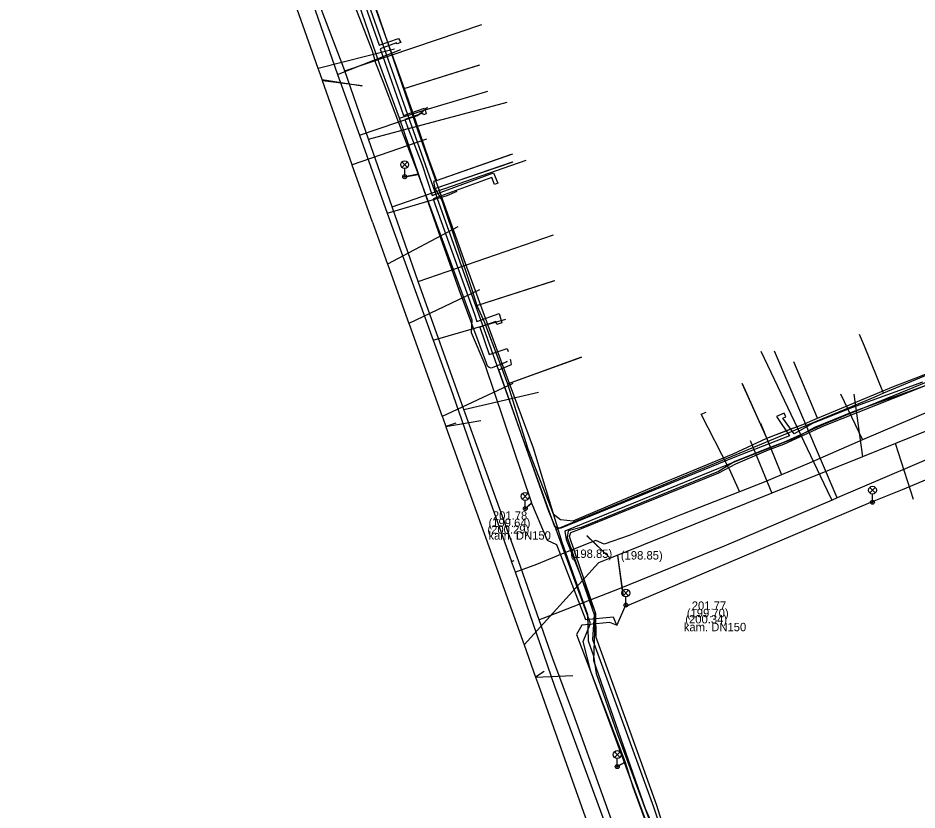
# Model space of a CAD drawing. Extents: x -596228 to -595156, y -1161235 to -1159373.
# Drawn here: x -596054.9 to -595969.3, y -1160804.7 to -1160729.3 of the extents above; entities that cross this region are included whole.
import ezdxf

# ---------------------------------------------------------------- set-up
doc = ezdxf.new("R2010")
doc.units = 0
for name, color, linetype in [('Vrstva 1', 7, 'Continuous'), ('Vrstva 12', 7, 'Continuous'), ('Vrstva 14', 7, 'Continuous'), ('Vrstva 19', 7, 'Continuous'), ('Vrstva 33', 7, 'Continuous'), ('Vrstva 42', 7, 'Continuous'), ('Vrstva 44', 7, 'Continuous'), ('Vrstva 55', 7, 'Continuous'), ('Vrstva 58', 7, 'Continuous'), ('Vrstva 9', 7, 'Continuous')]:
    doc.layers.add(name, color=color, linetype=linetype)

msp = doc.modelspace()

# ---------------------------------------------------------------- linework, layer by layer
at = {"layer": 'Vrstva 1'}
for p, q in [((-596025.96, -1160735.15), (-596022.13, -1160735.76)), ((-596022.13, -1160735.76), (-596025.918, -1160735.267)), ((-596014.19, -1160768.15), (-596010.85, -1160767.6)), ((-596013.241, -1160767.843), (-596014.193, -1160768.15)), ((-596000.757, -1160778.554), (-595998.525, -1160780.718)), ((-596000.75, -1160778.55), (-595998.541, -1160780.7)), ((-595997.27, -1160784.29), (-595997.808, -1160780.405)), ((-595997.305, -1160784.256), (-595997.803, -1160780.443)), ((-596004.814, -1160791.464), (-596005.64, -1160792.03)), ((-596005.64, -1160792.03), (-596002.09, -1160791.85))]:
    msp.add_line(p, q, dxfattribs=at)
at = {"layer": 'Vrstva 12'}
for p, q in [((-596021.38, -1160727.03), (-596018.16, -1160735.99)), ((-596018.16, -1160735.99), (-596011.08, -1160733.8)), ((-596015.23, -1160745.51), (-596007.79, -1160742.97)), ((-596015.06, -1160744.76), (-596008.03, -1160742.3)), ((-596011.22, -1160756.65), (-596003.8, -1160754.27)), ((-595974.35, -1160760.51), (-595974.81, -1160759.4)), ((-595972.52, -1160765), (-595974.35, -1160760.51)), ((-596008.32, -1160764.12), (-596001.23, -1160761.55)), ((-595978.8, -1160767.38), (-595981.05, -1160762.01)), ((-595983.64, -1160769.26), (-595985.97, -1160764.06)), ((-595972.52, -1160765), (-595973.44, -1160765.39)), ((-595983.64, -1160769.26), (-595981.42, -1160768.41))]:
    msp.add_line(p, q, dxfattribs=at)
for points in [[(-596024.14, -1160720.6), (-596014.84, -1160746.91), (-596010.57, -1160758.88), (-596004.4, -1160776.22)], [(-596018.16, -1160735.99), (-596017.34, -1160738.26), (-596017.02, -1160739.26), (-596015.82, -1160742.7), (-596015.06, -1160744.76)], [(-596015.06, -1160744.76), (-596015.35, -1160744.86), (-596015.23, -1160745.51)], [(-596015.23, -1160745.51), (-596014.57, -1160746.63), (-596011.67, -1160755.24), (-596011.22, -1160756.65)], [(-595951.56, -1160749.63), (-595949.17, -1160755.35), (-595965.3, -1160761.99), (-595972.52, -1160765)], [(-596011.22, -1160756.65), (-596010.51, -1160758.27), (-596009.14, -1160761.87), (-596008.32, -1160764.12)], [(-595978.8, -1160767.38), (-595971.58, -1160764.35), (-595969.02, -1160763.37), (-595965.59, -1160761.98)], [(-596008.32, -1160764.12), (-596006.38, -1160770.28), (-596003.96, -1160776.49), (-596003.27, -1160777.02), (-596002.06, -1160777.14), (-595994.12, -1160773.77), (-595986.83, -1160770.75), (-595983.64, -1160769.26)], [(-595973.44, -1160765.39), (-595992.4, -1160773.28), (-596002.75, -1160777.59), (-596003.67, -1160777.98)], [(-595981.42, -1160768.41), (-595980.22, -1160767.96), (-595978.8, -1160767.38)], [(-596004.4, -1160776.22), (-596004.05, -1160777.06), (-596003.67, -1160777.98)], [(-595993.13, -1160811.14), (-596000.37, -1160791.47), (-596001.1, -1160788.61), (-596000.4, -1160786.92), (-596003.67, -1160777.98)]]:
    msp.add_lwpolyline(points, dxfattribs=at)
at = {"layer": 'Vrstva 14'}
for p, q in [((-596023.81, -1160734.32), (-596010.759, -1160729.9)), ((-596021.55, -1160740.81), (-596008.335, -1160737.297)), ((-596019.3, -1160747.25), (-596006.526, -1160742.818)), ((-596016.81, -1160754.38), (-596003.95, -1160749.943)), ((-596012.47, -1160766.55), (-596005.354, -1160764.891)), ((-595997.69, -1160783.61), (-596004.96, -1160786.419)), ((-596004.96, -1160786.419), (-596005.316, -1160786.55))]:
    msp.add_line(p, q, dxfattribs=at)
for points in [[(-596005.316, -1160786.55), (-596007.28, -1160780.96), (-596012.47, -1160766.55), (-596016.81, -1160754.38), (-596019.3, -1160747.25), (-596021.55, -1160740.81), (-596023.81, -1160734.32), (-596025.95, -1160728.69), (-596029.94, -1160717.49), (-596032.44, -1160710.28), (-596035.58, -1160701.23), (-596036.84, -1160697.66), (-596039.83, -1160689.21), (-596042.1, -1160682.66), (-596044.23, -1160676.62), (-596049.04, -1160662.69), (-596049.3, -1160662.04), (-596049.763, -1160661.541)], [(-595895.93, -1160740.59), (-595899.6, -1160742.31), (-595912.84, -1160747.84), (-595914.74, -1160748.68), (-595921.25, -1160751.56), (-595923.91, -1160752.66), (-595927.19, -1160754.01), (-595932.66, -1160756.26), (-595933.82, -1160756.75), (-595937.68, -1160758.4), (-595942.37, -1160760.37), (-595945.06, -1160761.51), (-595946.46, -1160762.1), (-595947.85, -1160762.68), (-595962.12, -1160768.63), (-595963.29, -1160769.12), (-595970.02, -1160772), (-595976.93, -1160774.96), (-595977.43, -1160775.17), (-595987.69, -1160779.56), (-595997.69, -1160783.61)], [(-595977.43, -1160775.17), (-595977.53, -1160774.94), (-595984.171, -1160761.044)], [(-595976.93, -1160774.96), (-595977.03, -1160774.73), (-595982.919, -1160760.992)], [(-595970.51, -1160883.7), (-595971.34, -1160881.48), (-595971.678, -1160880.585), (-595977.044, -1160866.381), (-595977.65, -1160864.74), (-595981.27, -1160854.23), (-595984.42, -1160845.33), (-595988.277, -1160834.354), (-595988.37, -1160834.09), (-595988.6, -1160833.43), (-595990.35, -1160828.3), (-595994.34, -1160816.87), (-595996.507, -1160810.871), (-596002.04, -1160795.55), (-596004, -1160790.26), (-596005.316, -1160786.55)]]:
    msp.add_lwpolyline(points, dxfattribs=at)
at = {"layer": 'Vrstva 19'}
for p, q in [((-596024.5, -1160734.68), (-596018.46, -1160732.3)), ((-596015.39, -1160759.94), (-596008.47, -1160757.96)), ((-595976.62, -1160765.06), (-595974.54, -1160769.42)), ((-595984.24, -1160767.85), (-595982.9, -1160771.13)), ((-595982.9, -1160771.13), (-595982.24, -1160772.75)), ((-595987.25, -1160772.13), (-595986.25, -1160774.38)), ((-596007.92, -1160781.01), (-596007.68, -1160780.92))]:
    msp.add_line(p, q, dxfattribs=at)
for points in [[(-596054.9, -1160660.2), (-596054.36, -1160661.04), (-596054.05, -1160661.51), (-596053.9, -1160661.74), (-596052.09, -1160664.28), (-596048.45, -1160666.9), (-596046.42, -1160672.55), (-596043.81, -1160679.84), (-596042.99, -1160682.32), (-596040.41, -1160689.82), (-596037.35, -1160698.34), (-596036.37, -1160701.32), (-596032.54, -1160711.83), (-596031.38, -1160715.08), (-596026.89, -1160727.72), (-596024.5, -1160734.68), (-596022.39, -1160740.45), (-596019.76, -1160747.88), (-596015.39, -1160759.94), (-596013.75, -1160764.5), (-596010.59, -1160773.53), (-596007.92, -1160781.01)], [(-596022.39, -1160740.45), (-596016.88, -1160738.57), (-596015.92, -1160737.77)], [(-596019.76, -1160747.88), (-596014.04, -1160746.19), (-596013.1, -1160745.78)], [(-595967.9, -1160766.61), (-595974.54, -1160769.42), (-595979.62, -1160771.65), (-595982.24, -1160772.75), (-595983.9, -1160773.45), (-595986.25, -1160774.38), (-595991.65, -1160776.51), (-595996.72, -1160778.52), (-595999.1, -1160779.36), (-595999.92, -1160779.01), (-596000.49, -1160779.22)], [(-595987.25, -1160772.13), (-595989.88, -1160766.99), (-595989.42, -1160766.8)], [(-596000.49, -1160779.22), (-596003.26, -1160780.35), (-596003.72, -1160780.54), (-596005.56, -1160781.28), (-596007.55, -1160782.04)], [(-595973.14, -1160878.6), (-595975.4, -1160872.46), (-595980.42, -1160858.45), (-595981.3, -1160855.86), (-595985.54, -1160844), (-595987.88, -1160837.26), (-595990.29, -1160830.5), (-595991.79, -1160826.36), (-595994.69, -1160818.13), (-595997.31, -1160810.58), (-596003.82, -1160792.91), (-596007.55, -1160782.04), (-596007.92, -1160781.01)]]:
    msp.add_lwpolyline(points, dxfattribs=at)
at = {"layer": 'Vrstva 33'}
for p, q in [((-596018.365, -1160742.985), (-596017.835, -1160743.515)), ((-596018.365, -1160743.515), (-596017.835, -1160742.985)), ((-596018.1, -1160744.4), (-596018.1, -1160743.625)), ((-596006.895, -1160774.555), (-596006.365, -1160775.085)), ((-596006.895, -1160775.085), (-596006.365, -1160774.555)), ((-595973.845, -1160773.955), (-595973.315, -1160774.485)), ((-595973.845, -1160774.485), (-595973.315, -1160773.955)), ((-595973.58, -1160775.37), (-595973.58, -1160774.595)), ((-596006.63, -1160775.97), (-596006.63, -1160775.195)), ((-595997.315, -1160783.745), (-595996.785, -1160784.275)), ((-595997.315, -1160784.275), (-595996.785, -1160783.745)), ((-595997.05, -1160785.16), (-595997.05, -1160784.385)), ((-595998.135, -1160799.115), (-595997.605, -1160799.645)), ((-595998.135, -1160799.645), (-595997.605, -1160799.115)), ((-595997.87, -1160800.53), (-595997.87, -1160799.755))]:
    msp.add_line(p, q, dxfattribs=at)
for centre, radius in [((-596018.1, -1160743.25), 0.375), ((-596018.1, -1160744.4), 0.19), ((-596018.1, -1160744.4), 0.05), ((-596006.63, -1160774.82), 0.375), ((-595973.58, -1160774.22), 0.375), ((-595973.58, -1160775.37), 0.19), ((-595973.58, -1160775.37), 0.05), ((-596006.63, -1160775.97), 0.19), ((-596006.63, -1160775.97), 0.05), ((-595997.05, -1160784.01), 0.375), ((-595997.05, -1160785.16), 0.19), ((-595997.05, -1160785.16), 0.05), ((-595997.87, -1160799.38), 0.375), ((-595997.87, -1160800.53), 0.19), ((-595997.87, -1160800.53), 0.05)]:
    msp.add_circle(centre, radius, dxfattribs=at)
at = {"layer": 'Vrstva 42'}
for points in [[(-596008.4, -1160761.909), (-596008.382, -1160762.025), (-596009.294, -1160762.383), (-596009.872, -1160762.602), (-596010.048, -1160762.561), (-596010.227, -1160762.42), (-596010.312, -1160762.139), (-596012.916, -1160755.166), (-596014.645, -1160750.249), (-596016.27, -1160745.599), (-596018.581, -1160738.823), (-596020.464, -1160733.753), (-596023.193, -1160725.807)], [(-596021.816, -1160728.189), (-596020.542, -1160731.878), (-596018.686, -1160731.24), (-596018.466, -1160731.631), (-596018.828, -1160731.754), (-596018.89, -1160731.644), (-596020.44, -1160732.216), (-596018.207, -1160738.558), (-596016.199, -1160737.89), (-596016.155, -1160738.042), (-596016.046, -1160738.42), (-596016.314, -1160738.515), (-596016.372, -1160738.349), (-596018.083, -1160738.958), (-596017.725, -1160739.917), (-596016.426, -1160743.274), (-596015.484, -1160746.181), (-596009.661, -1160744.016), (-596009.244, -1160745.005), (-596009.379, -1160745.063), (-596009.554, -1160745.127), (-596009.813, -1160744.48), (-596015.375, -1160746.516), (-596015.203, -1160747.072), (-596011.45, -1160757.467), (-596011.228, -1160758.181), (-596009.112, -1160757.407), (-596008.839, -1160758.296), (-596009.049, -1160758.371), (-596009.328, -1160758.452), (-596009.426, -1160758.163), (-596010.955, -1160758.723), (-596010.058, -1160761.31), (-596008.358, -1160760.743), (-596008.241, -1160761.029)], [(-596018.581, -1160738.823), (-596016.948, -1160738.278), (-596016.155, -1160738.042), (-596010.196, -1160736.265)], [(-595936.437, -1160750.624), (-595944.861, -1160754.206), (-595948.324, -1160755.834), (-595955.478, -1160758.746), (-595964.783, -1160762.531), (-595968.658, -1160764.323), (-595975.348, -1160766.734), (-595979.104, -1160768.254), (-595980.872, -1160769.232), (-595986.529, -1160771.469), (-596002.845, -1160778.125), (-596002.718, -1160778.924), (-595999.968, -1160785.818), (-596000.123, -1160790.427), (-595995.215, -1160804.501), (-595993.599, -1160808.162)], [(-595968.81, -1160763.953), (-595975.491, -1160766.36), (-595979.276, -1160767.892), (-595981.043, -1160768.87), (-595982.114, -1160767.377), (-595981.821, -1160767.245), (-595981.983, -1160766.888), (-595982.707, -1160767.211), (-595981.481, -1160769.058), (-595986.678, -1160771.098), (-596003.29, -1160777.874), (-596003.799, -1160777.702), (-596006.784, -1160769.464), (-596009.152, -1160762.777), (-596007.923, -1160762.278), (-596007.999, -1160761.876), (-596008.015, -1160761.797)]]:
    msp.add_lwpolyline(points, dxfattribs=at)
at = {"layer": 'Vrstva 44'}
for points in [[(-596044.407, -1160658.749), (-596044.407, -1160659.489), (-596044.78, -1160660.763), (-596045.116, -1160662.461), (-596044.947, -1160663.652), (-596042.285, -1160669.135), (-596039.373, -1160677.719), (-596035.806, -1160687.157), (-596031.152, -1160700.122), (-596025.855, -1160714.324), (-596020.86, -1160728.376), (-596016.841, -1160740.026), (-596012.352, -1160752.637), (-596008.974, -1160761.837), (-596005.865, -1160770.199), (-596003.139, -1160779.18), (-596000.707, -1160786.059), (-596000.627, -1160788.552), (-596000.125, -1160789.971), (-595999.871, -1160791.658), (-595997.88, -1160797.373), (-595993.924, -1160808.037)], [(-595947.138, -1160755.147), (-595947.53, -1160755.263), (-595955.361, -1160758.509), (-595961.279, -1160761.006), (-595966.257, -1160762.968), (-595968.492, -1160763.968), (-595978.248, -1160767.963), (-595982.038, -1160769.681), (-595983.515, -1160770.213), (-595986.68, -1160771.502), (-595988.239, -1160772.436), (-596001.296, -1160777.768), (-596002.534, -1160778.092), (-596002.636, -1160778.737), (-596000.076, -1160786.064), (-596000.212, -1160788.42), (-595994.428, -1160804.351), (-595993.163, -1160808.12)], [(-595992.914, -1160808.002), (-595994.102, -1160804.235), (-595996.628, -1160797.175), (-595999.888, -1160788.242), (-595999.901, -1160785.985), (-596002.42, -1160778.617), (-596002.297, -1160778.256), (-596001.26, -1160777.87), (-595988.213, -1160772.576), (-595986.599, -1160771.708), (-595983.467, -1160770.39), (-595982.005, -1160769.834), (-595978.161, -1160768.068), (-595968.389, -1160764.21), (-595966.12, -1160763.24), (-595961.236, -1160761.203), (-595955.248, -1160758.714), (-595947.498, -1160755.415), (-595947.062, -1160755.333)]]:
    msp.add_lwpolyline(points, dxfattribs=at)
at = {"layer": 'Vrstva 55'}
for points in [[(-596023.21, -1160727.17), (-596021.19, -1160732.42), (-596020.87, -1160733.56), (-596020.16, -1160735.4), (-596016.8, -1160744.17), (-596018.1, -1160744.4), (-596016.8, -1160744.18), (-596011.7, -1160758.02), (-596011.78, -1160759.23), (-596010.48, -1160762.26), (-596006.04, -1160775.44), (-596006.63, -1160775.97), (-596006.04, -1160775.45), (-596004.53, -1160778.97), (-596003.65, -1160779.39), (-596000.9, -1160786.54), (-595998.26, -1160786.29), (-595997.94, -1160787.06)], [(-595997.912, -1160787.109), (-595997.92, -1160787.09), (-595997.1, -1160785.28), (-595997.05, -1160785.16), (-595996.952, -1160785.217), (-595973.721, -1160775.358), (-595973.58, -1160775.37), (-595973.586, -1160775.302), (-595970.72, -1160774.17), (-595963.24, -1160771.03)], [(-595997.94, -1160787.06), (-595998.56, -1160786.82), (-596001.24, -1160787.07), (-596001.75, -1160787.95), (-595997.12, -1160800.1), (-595997.87, -1160800.53), (-595997.11, -1160800.1), (-595996.38, -1160802.44), (-595994.84, -1160806.7)]]:
    msp.add_lwpolyline(points, dxfattribs=at)
at = {"layer": 'Vrstva 58'}
for p, q in [((-596021.38, -1160727.03), (-596018.16, -1160735.99)), ((-596018.16, -1160735.99), (-596010.94, -1160733.75)), ((-596015.23, -1160745.52), (-596007.83, -1160742.99)), ((-596015.06, -1160744.76), (-596007.81, -1160742.22)), ((-596011.22, -1160756.65), (-596003.84, -1160754.28)), ((-596008.32, -1160764.12), (-596001.28, -1160761.56)), ((-595978.8, -1160767.38), (-595981.05, -1160762.01)), ((-595983.64, -1160769.26), (-595985.95, -1160764.1))]:
    msp.add_line(p, q, dxfattribs=at)
for points in [[(-596018.16, -1160735.99), (-596017.34, -1160738.26), (-596017.02, -1160739.26), (-596015.82, -1160742.7), (-596015.06, -1160744.76)], [(-596015.06, -1160744.76), (-596015.35, -1160744.86), (-596015.23, -1160745.52)], [(-596015.23, -1160745.52), (-596014.57, -1160746.63), (-596011.67, -1160755.24), (-596011.22, -1160756.65)], [(-596011.22, -1160756.65), (-596010.51, -1160758.27), (-596009.14, -1160761.87), (-596008.32, -1160764.12)], [(-595978.8, -1160767.38), (-595971.58, -1160764.35), (-595969.02, -1160763.37), (-595965.59, -1160761.98)], [(-596008.32, -1160764.12), (-596006.38, -1160770.28), (-596003.96, -1160776.49), (-596003.27, -1160777.02), (-596002.06, -1160777.14), (-595994.12, -1160773.78), (-595986.83, -1160770.75), (-595983.64, -1160769.26)], [(-595983.64, -1160769.26), (-595980.22, -1160767.96), (-595978.8, -1160767.38)]]:
    msp.add_lwpolyline(points, dxfattribs=at)
at = {"layer": 'Vrstva 9'}
for p, q in [((-596019.06, -1160732.256), (-596026.327, -1160734.111)), ((-596016.021, -1160740.819), (-596023.094, -1160743.258)), ((-596013.055, -1160749.154), (-596019.73, -1160752.714)), ((-596010.98, -1160755.148), (-596017.704, -1160758.361)), ((-596007.794, -1160764.075), (-596014.53, -1160767.21)), ((-595975.365, -1160765.082), (-595974.531, -1160771.04)), ((-595985.224, -1160769.491), (-595983.15, -1160774.508)), ((-595969.68, -1160775.11), (-595971.386, -1160769.775)), ((-595999.654, -1160781.148), (-596006.731, -1160788.952))]:
    msp.add_line(p, q, dxfattribs=at)
for points in [[(-596021.162, -1160748.723), (-596023.083, -1160743.288), (-596023.094, -1160743.258), (-596025.918, -1160735.266), (-596025.961, -1160735.146), (-596026.24, -1160734.358), (-596026.327, -1160734.111), (-596029.953, -1160723.853), (-596029.993, -1160723.739), (-596033.405, -1160714.089), (-596033.426, -1160714.028), (-596033.743, -1160713.133), (-596033.76, -1160713.084), (-596034.092, -1160712.142), (-596034.1, -1160712.12), (-596037.482, -1160702.553)], [(-596021.162, -1160748.723), (-596019.73, -1160752.714), (-596019.71, -1160752.769), (-596017.704, -1160758.361), (-596017.684, -1160758.417), (-596014.53, -1160767.21), (-596014.48, -1160767.35), (-596014.193, -1160768.15), (-596014.176, -1160768.197), (-596006.731, -1160788.952)], [(-595968.251, -1160768.513), (-595971.386, -1160769.775), (-595974.531, -1160771.04), (-595983.15, -1160774.508), (-595997.808, -1160780.406), (-595998.541, -1160780.7), (-595999.654, -1160781.148)], [(-596006.731, -1160788.952), (-596005.64, -1160792.03), (-596005.371, -1160792.786), (-595998.261, -1160812.808), (-595998.227, -1160812.903), (-595997.04, -1160816.248), (-595996.739, -1160817.095), (-595996.726, -1160817.132), (-595993.794, -1160825.389), (-595993.78, -1160825.428), (-595990.97, -1160833.35), (-595990.933, -1160833.454), (-595989.787, -1160836.676), (-595989.761, -1160836.749), (-595988.486, -1160840.245)]]:
    msp.add_lwpolyline(points, dxfattribs=at)

# ---------------------------------------------------------------- texts
at = {"layer": 'Vrstva 12'}
for s, p in [('201.78', (-596009.707, -1160777.037)), ('(199.64)', (-596010.122, -1160777.723)), ('(200.29)', (-596010.227, -1160778.365)), ('kam. DN150', (-596010.129, -1160778.93)), ('(198.85)', (-596002.33, -1160780.67)), ('(198.85)', (-595997.527, -1160780.823)), ('201.77', (-595990.777, -1160785.608)), ('(199.70)', (-595991.252, -1160786.314)), ('(200.34)', (-595991.397, -1160786.9)), ('kam. DN150', (-595991.539, -1160787.646))]:
    msp.add_text(s, height=0.8, dxfattribs=at).set_placement(p)

doc.saveas('drawing.dxf')
